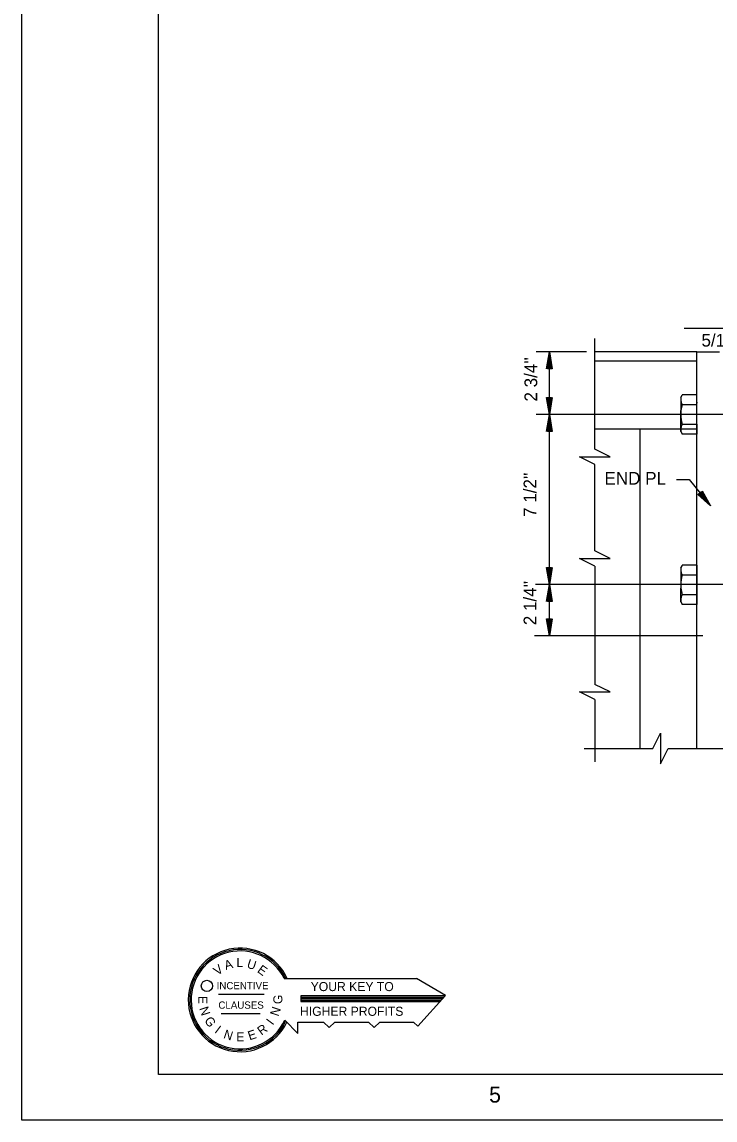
# Model space of a CAD drawing. Extents: x 0.1 to 13.5, y 0.1 to 9.5.
# Drawn here: x 0.124 to 2.665, y 0.124 to 4.152 of the extents above; entities that cross this region are included whole.
import ezdxf

# ---------------------------------------------------------------- set-up
doc = ezdxf.new("R2010")
doc.units = 0
for name, color, linetype in [('Level 1', 7, 'Continuous'), ('Level 2', 7, 'Continuous'), ('Level 25', 7, 'Continuous'), ('Level 3', 7, 'Continuous'), ('Level 4', 7, 'Continuous'), ('Level 50', 7, 'Continuous')]:
    doc.layers.add(name, color=color, linetype=linetype)

msp = doc.modelspace()

# ---------------------------------------------------------------- linework, layer by layer
at = {"layer": 'Level 1'}
for p, q in [((1.0849, 0.6432), (1.5706, 0.6432)), ((1.6766, 0.5806), (1.5706, 0.6432)), ((0.8449, 0.5849), (1.0113, 0.5849)), ((1.6753, 0.5789), (1.1466, 0.5789)), ((1.1466, 0.5789), (1.1466, 0.5582)), ((1.6699, 0.5732), (1.1466, 0.5732)), ((1.6653, 0.5679), (1.1466, 0.5679)), ((1.6766, 0.5806), (1.5756, 0.4676)), ((1.6603, 0.5622), (1.1466, 0.5622)), ((1.1466, 0.5582), (1.6566, 0.5582)), ((0.8536, 0.5146), (0.9976, 0.5146)), ((1.0873, 0.4899), (1.1356, 0.4416)), ((1.1356, 0.4416), (1.1356, 0.4832)), ((1.1356, 0.4832), (1.2293, 0.4832)), ((1.2293, 0.4832), (1.2499, 0.4626)), ((1.2499, 0.4626), (1.2706, 0.4832)), ((1.2706, 0.4832), (1.3946, 0.4832)), ((1.3946, 0.4832), (1.4153, 0.4626)), ((1.4153, 0.4626), (1.4359, 0.4832)), ((1.4359, 0.4832), (1.5599, 0.4832)), ((1.5599, 0.4832), (1.5756, 0.4676))]:
    msp.add_line(p, q, dxfattribs=at)
for points in [[(0.1238, 9.4569), (13.4571, 9.4569), (13.4571, 0.1236), (0.1238, 0.1236)], [(0.6238, 9.2903), (13.2904, 9.2903), (13.2904, 0.2903), (0.6238, 0.2903)]]:
    msp.add_lwpolyline(points, close=True, dxfattribs=at)
for points in [[(2.2242, 2.5287), (2.1679, 2.5566), (2.2803, 2.5566), (2.2242, 2.5847)], [(2.2242, 2.1554), (2.1679, 2.1834), (2.2803, 2.1834), (2.2242, 2.2115)], [(2.2242, 1.6658), (2.1679, 1.6938), (2.2803, 1.6938), (2.2242, 1.7219)], [(2.4371, 1.4864), (2.465, 1.5426), (2.465, 1.4303), (2.4932, 1.4864)]]:
    msp.add_lwpolyline(points, dxfattribs=at)
msp.add_circle((0.8018, 0.6157), 0.0205, dxfattribs=at)
for radius, start, end in [(0.19, 24.569, 334.4243), (0.1848, 25.3095, 334.4522), (0.1796, 26.0896, 335.5943)]:
    msp.add_arc((0.9236, 0.5642), radius, start, end, dxfattribs=at)
at = {"layer": 'Level 2'}
for p, q in [((2.2242, 2.5847), (2.2242, 2.9905)), ((2.1938, 2.9413), (2.0097, 2.9413)), ((2.0575, 2.7118), (2.0575, 2.9413)), ((2.5977, 2.9413), (2.2242, 2.9413)), ((2.5977, 1.4864), (2.5977, 2.9413)), ((2.5977, 2.9075), (2.2242, 2.9075)), ((2.5392, 2.7747), (2.5448, 2.7844)), ((2.5977, 2.7844), (2.5448, 2.7844)), ((2.5977, 2.6399), (2.5977, 2.7844)), ((2.5392, 2.7747), (2.5392, 2.7267)), ((2.5446, 2.7484), (2.5977, 2.7484)), ((2.6003, 2.754), (2.5977, 2.754)), ((2.0575, 2.0876), (2.0575, 2.7118)), ((2.5392, 2.7122), (2.5392, 2.7267)), ((2.5392, 2.6496), (2.5392, 2.7122)), ((2.5446, 2.676), (2.5977, 2.676)), ((2.5977, 2.6765), (2.5977, 2.6399)), ((2.6003, 2.6703), (2.5977, 2.6703)), ((2.5977, 2.6575), (2.2242, 2.6575)), ((2.3894, 2.6575), (2.3894, 1.4864)), ((2.5392, 2.6496), (2.5448, 2.6399)), ((2.5977, 2.6399), (2.5448, 2.6399)), ((2.2242, 2.1554), (2.2242, 1.7219)), ((2.5392, 2.1497), (2.5448, 2.1594)), ((2.5392, 2.1497), (2.5392, 2.0872)), ((2.5977, 2.1594), (2.5448, 2.1594)), ((2.5977, 2.1594), (2.5977, 2.0149)), ((2.5977, 2.1228), (2.5977, 2.1594)), ((2.5446, 2.1233), (2.5977, 2.1233)), ((2.6003, 2.129), (2.5977, 2.129)), ((2.0575, 1.8997), (2.0575, 2.0876)), ((2.5392, 2.0872), (2.5392, 2.0743)), ((2.5392, 2.0246), (2.5392, 2.0743)), ((2.5392, 2.0246), (2.5448, 2.0149)), ((2.5446, 2.051), (2.5977, 2.051)), ((2.5977, 2.0149), (2.5448, 2.0149)), ((2.6003, 2.0453), (2.5977, 2.0453)), ((2.2242, 1.6658), (2.2242, 1.4382)), ((2.1852, 1.4864), (2.4371, 1.4864)), ((2.4932, 1.4864), (2.7152, 1.4864))]:
    msp.add_line(p, q, dxfattribs=at)
for centre, radius, start, end in [((2.5705, 2.7661), 0.0314, 149.7124, 214.511), ((2.6646, 2.7117), 0.1255, 163.0196, 173.1312), ((2.6646, 2.7117), 0.1255, 173.1312, 179.7886), ((2.6646, 2.7117), 0.1255, 179.7886, 196.4948), ((2.5705, 2.6582), 0.0314, 145.489, 210.2876), ((2.5705, 2.1411), 0.0314, 149.7124, 214.511), ((2.6646, 2.0876), 0.1255, 163.5052, 180.2114), ((2.6646, 2.0876), 0.1255, 180.2114, 186.1219), ((2.6646, 2.0876), 0.1255, 186.1219, 196.9804), ((2.5705, 2.0332), 0.0314, 145.489, 210.2876)]:
    msp.add_arc(centre, radius, start, end, dxfattribs=at)
at = {"layer": 'Level 25'}
for p, q in [((2.5977, 2.9413), (2.681, 2.9413)), ((2.2242, 2.2115), (2.2242, 2.5287))]:
    msp.add_line(p, q, dxfattribs=at)
at = {"layer": 'Level 3'}
for p, q in [((2.9105, 2.7118), (2.0097, 2.7118)), ((2.0575, 2.7291), (2.0575, 2.7291)), ((2.0575, 2.7118), (2.0575, 2.7118)), ((2.0575, 2.7118), (2.0575, 2.7118)), ((2.0575, 2.6944), (2.0575, 2.6944)), ((2.6379, 2.3902), (2.6379, 2.3902)), ((2.6488, 2.3768), (2.6488, 2.3768)), ((2.0575, 2.1049), (2.0575, 2.1049)), ((2.9105, 2.0876), (2.0065, 2.0876)), ((2.0575, 2.0876), (2.0575, 2.0876)), ((2.0575, 2.0876), (2.0575, 2.0876)), ((2.0575, 2.0702), (2.0575, 2.0702)), ((2.6202, 1.8997), (2.0032, 1.8997)), ((2.0575, 1.917), (2.0575, 1.917)), ((2.0575, 1.8997), (2.0575, 1.8997))]:
    msp.add_line(p, q, dxfattribs=at)
for points in [[(2.0679, 2.7741), (2.0575, 2.7118), (2.0472, 2.7741), (2.0649, 2.7741), (2.0575, 2.7291), (2.0505, 2.7714), (2.0619, 2.7714), (2.0575, 2.7458), (2.0539, 2.7688), (2.0585, 2.7688), (2.0575, 2.7631)], [(2.0472, 2.6494), (2.0575, 2.7118), (2.0679, 2.6494), (2.0502, 2.6494), (2.0575, 2.6944), (2.0645, 2.6521), (2.0532, 2.6521), (2.0575, 2.6778), (2.0612, 2.6548), (2.0565, 2.6548), (2.0575, 2.6604)], [(2.5242, 2.4728), (2.5703, 2.4728), (2.6488, 2.3768)], [(2.6174, 2.4316), (2.6488, 2.3768), (2.6014, 2.4185), (2.6151, 2.4297), (2.6379, 2.3902), (2.6056, 2.4186), (2.6144, 2.4257), (2.6273, 2.4031), (2.6099, 2.4186), (2.6135, 2.4216), (2.6163, 2.4165)], [(2.0679, 2.1499), (2.0575, 2.0876), (2.0472, 2.1499), (2.0649, 2.1499), (2.0575, 2.1049), (2.0505, 2.1472), (2.0619, 2.1472), (2.0575, 2.1216), (2.0539, 2.1446), (2.0585, 2.1446), (2.0575, 2.1389)], [(2.0472, 2.0252), (2.0575, 2.0876), (2.0679, 2.0252), (2.0502, 2.0252), (2.0575, 2.0702), (2.0645, 2.0279), (2.0532, 2.0279), (2.0575, 2.0536), (2.0612, 2.0306), (2.0565, 2.0306), (2.0575, 2.0362)], [(2.0679, 1.962), (2.0575, 1.8997), (2.0472, 1.962), (2.0649, 1.962), (2.0575, 1.917), (2.0505, 1.9593), (2.0619, 1.9593), (2.0575, 1.9337), (2.0539, 1.9567), (2.0585, 1.9567), (2.0575, 1.951)]]:
    msp.add_lwpolyline(points, dxfattribs=at)
at = {"layer": 'Level 4'}
msp.add_line((2.9274, 3.0273), (2.5523, 3.0273), dxfattribs=at)
at = {"layer": 'Level 50'}
for p, q in [((2.0575, 2.9413), (2.0575, 2.9413)), ((2.0575, 2.9413), (2.0575, 2.9413)), ((2.0575, 2.924), (2.0575, 2.924)), ((2.0575, 2.924), (2.0575, 2.924))]:
    msp.add_line(p, q, dxfattribs=at)
msp.add_lwpolyline([(2.0472, 2.879), (2.0575, 2.9413), (2.0679, 2.879), (2.0502, 2.879), (2.0575, 2.924), (2.0645, 2.8817), (2.0532, 2.8817), (2.0575, 2.9073), (2.0612, 2.8843), (2.0565, 2.8843), (2.0575, 2.89)], dxfattribs=at)
msp.add_lwpolyline([(2.0472, 2.879), (2.0575, 2.9413), (2.0679, 2.879), (2.0502, 2.879), (2.0575, 2.924), (2.0645, 2.8817), (2.0532, 2.8817), (2.0575, 2.9073), (2.0612, 2.8843), (2.0565, 2.8843), (2.0575, 2.89)], dxfattribs=at)

# ---------------------------------------------------------------- texts
at = {"layer": 'Level 1'}
for s, rotation, p in [('V', 35.9204, (0.8406, 0.6522)), ('A', 18.0731, (0.8716, 0.6736)), ('U', 342.1107, (0.9459, 0.6832)), ('E', 323.9298, (0.9839, 0.6682)), ('E', 270, (0.7699, 0.5789)), ('G', 90, (1.0786, 0.5489)), ('N', 288.0821, (0.7736, 0.5336)), ('N', 71.9179, (1.0639, 0.5019)), ('G', 306.0537, (0.7906, 0.4882)), ('I', 53.5836, (1.0433, 0.4692)), ('I', 323.5836, (0.8276, 0.4459)), ('N', 341.9179, (0.8603, 0.4249)), ('E', 18.2241, (0.9583, 0.4156)), ('R', 36.2206, (1.0019, 0.4326))]:
    msp.add_text(s, height=0.0333, rotation=rotation, dxfattribs=at).set_placement(p)
for s, height, p in [('L', 0.0333, (0.9099, 0.6846)), ('INCENTIVE', 0.02667, (0.8376, 0.6032)), ('YOUR KEY TO', 0.033333, (1.1823, 0.5966)), ('CLAUSES', 0.02667, (0.8439, 0.5319)), ('HIGHER PROFITS', 0.033333, (1.1433, 0.5059)), ('E', 0.0333, (0.9093, 0.4119)), ('5', 0.0584, (1.8366, 0.1876))]:
    msp.add_text(s, height=height, dxfattribs=at).set_placement(p)
at = {"layer": 'Level 3'}
for s, p in [('5/16', (2.6152, 2.9609)), ('END PL', (2.2597, 2.4544))]:
    msp.add_text(s, height=0.04667, dxfattribs=at).set_placement(p)
for s, p in [("2 3/4''", (2.0129, 2.7593)), ("7 1/2''", (2.0097, 2.3361)), ("2 1/4''", (2.0097, 1.9388))]:
    msp.add_text(s, height=0.04667, rotation=90, dxfattribs=at).set_placement(p)

doc.saveas('drawing.dxf')
